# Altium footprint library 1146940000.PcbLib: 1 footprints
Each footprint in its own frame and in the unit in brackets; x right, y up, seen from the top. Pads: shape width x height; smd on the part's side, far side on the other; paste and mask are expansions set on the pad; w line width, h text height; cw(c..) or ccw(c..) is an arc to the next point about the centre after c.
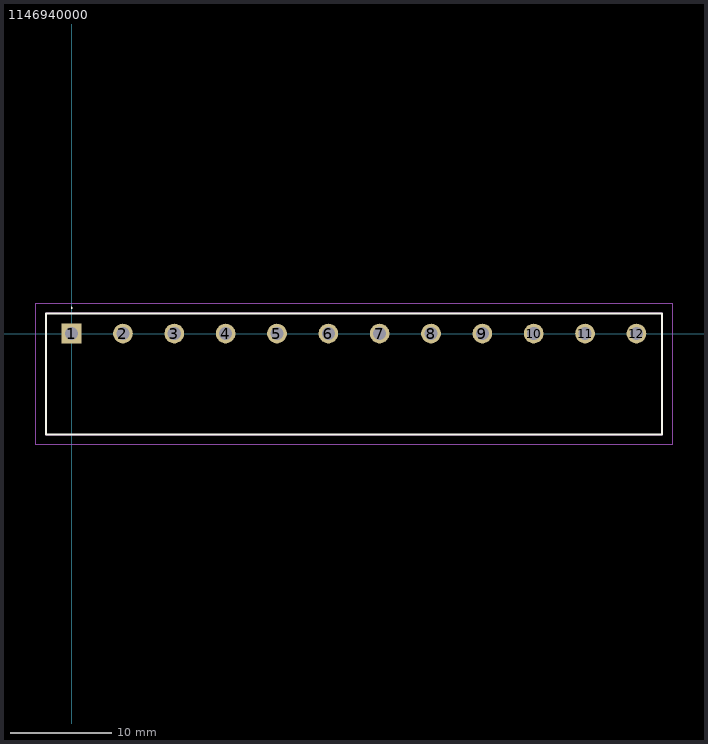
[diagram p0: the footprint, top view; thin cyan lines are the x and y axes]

## 1146940000 [mm]
pads (12):
  rect 1.95x1.95 hole 1.3: 1(0,0)
  round 1.95 hole 1.3: 2(5.08,0) 3(10.16,0) 4(15.24,0) 5(20.32,0) 6(25.4,0) 7(30.48,0) 8(35.56,0) 9(40.64,0) 10(45.72,0) 11(50.8,0) 12(55.88,0)
Top Overlay:
  lines w0.1: 0,2.5 cw(c0,2.55) 0,2.6 ; 0,2.5 0,2.5 ; 0,2.5 ccw(c0,2.55) 0,2.6 ; 0,2.6 0,2.6
  lines w0.2: -2.54,-10 58.42,-10 58.42,2 -2.54,2 -2.54,-10
Mechanical 15:
  lines w0.1: -2.54,-10 58.42,-10 58.42,2 -2.54,2 -2.54,-10
Mechanical 20:
  lines w0.1: -3.54,-11 59.42,-11 59.42,3 -3.54,3 -3.54,-11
